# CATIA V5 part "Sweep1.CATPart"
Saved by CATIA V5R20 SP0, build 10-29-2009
Part number: Part1
Bounding box of the stored display mesh (mm): x -100 to 397.653, y -100 to 398.625, z -213.081 to 213.018
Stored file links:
  J:\카티아자료\수업자료\툴바예제\6 GSD\Surfaces\Sweep1.CATPart
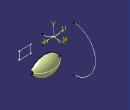
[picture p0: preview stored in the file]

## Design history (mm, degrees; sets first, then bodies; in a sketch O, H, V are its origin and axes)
Set1
  DatumCurve1 "Sketch.1"
  DatumCurve2 "Sketch.2"
Set2
  Sketch1 on xy-plane, origin (0, 0, 0), H (1, 0, 0), V (0, 1, 0)
    arc A1 centre (268.8402, 107.8697) radius 161.2039 from (397.653, 204.7921) to (130.8085, 191.1401) ccw
  Sketch2 on yz-plane, origin (0, 0, 0), H (0, 1, 0), V (0, 0, 1)
    arc A1 centre (184.9602, 0) radius 213.6712 from (200.8267, -213.0813) to (201.6492, 213.0184) ccw
    point P1 (184.9602, 0)
    coincidence: P1 H
  Sweep1: type Unspec, Profile Sketch1, Guide Sketch2
  Sketch3 on zx-plane, origin (0, 0, 0), H (-1, 0, 0), V (0, 0, 1)
    line L1 (-320.2975, 42.5205) -> (-209.0881, 42.5205)
    line L2 (-209.0881, 42.5205) -> (-209.0881, -29.9127)
    line L3 (-209.0881, -29.9127) -> (-320.2975, -29.9127)
    line L4 (-320.2975, -29.9127) -> (-320.2975, 42.5205)
    horizontal: L1 H, L3 H
    vertical: L2 V, L4 V
Body1 (main body)
  Pad1: profile Sketch3, direction (0, 1, 0), up to Sweep1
